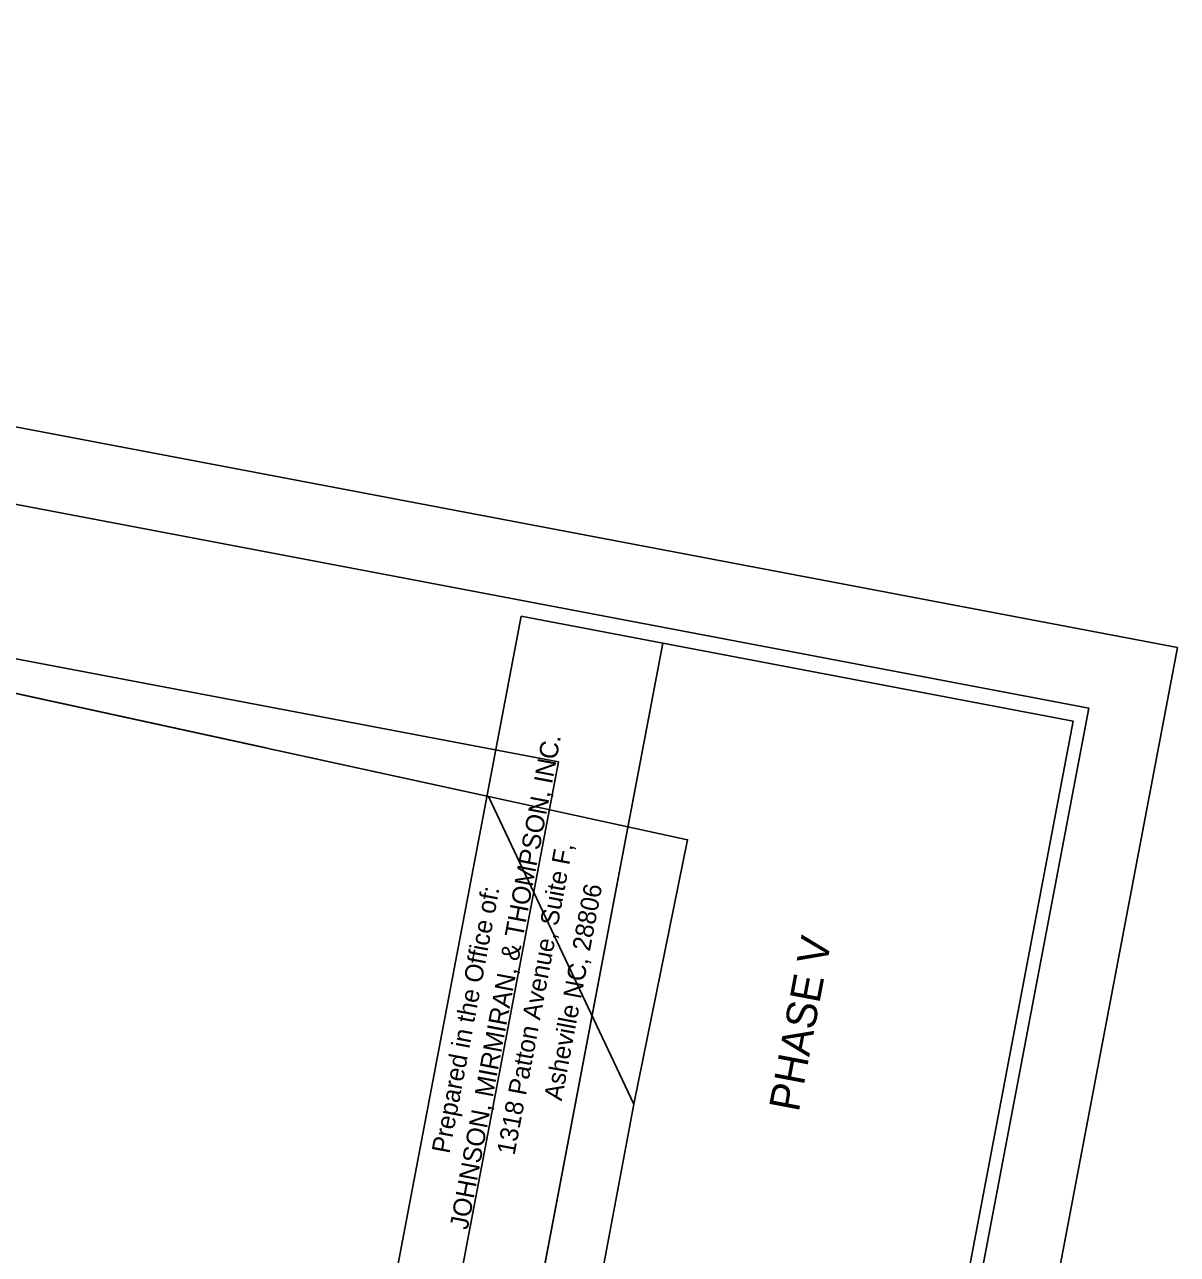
# Model space of a CAD drawing. Extents: x 1615680 to 1617075, y 898420 to 901168.
# Drawn here: x 1616695.7 to 1617075.3, y 900763.4 to 901168.4 of the extents above; entities that cross this region are included whole.
import ezdxf

# ---------------------------------------------------------------- set-up
doc = ezdxf.new("R2010")
doc.units = 0
for name, color, linetype in [('DEV BORDER CELL', 7, 'Continuous'), ('Matchline', 7, 'Continuous'), ('Scratch_Level_0', 7, 'Continuous'), ('Sheet Clip Boundary CELL', 7, 'Continuous'), ('Sheet Plan CELL', 7, 'Continuous'), ('Sheet Plot Border Outside CELL', 7, 'Continuous'), ('Sheet Sticker Preliminary CELL', 7, 'Continuous'), ('Sheet Title CELL', 7, 'Continuous')]:
    doc.layers.add(name, color=color, linetype=linetype)

msp = doc.modelspace()

# ---------------------------------------------------------------- linework, layer by layer
at = {"layer": 'DEV BORDER CELL'}
for points in [[(1616014.55, 901139.21), (1615734.74, 899665.53), (1616766.32, 899469.67), (1617046.12, 900943.35)], [(1616905.88, 900964.73), (1616861.86, 900732.87), (1616996.95, 900707.23), (1617040.97, 900939.08)]]:
    msp.add_lwpolyline(points, close=True, dxfattribs=at)
at = {"layer": 'Matchline'}
msp.add_line((1616176.29, 901060.7), (1616775.18, 900930.23), dxfattribs=at)
at = {"layer": 'Scratch_Level_0'}
msp.add_lwpolyline([(1616054.34, 901080.76), (1615793.19, 899705.33), (1616726.52, 899528.12), (1616890.46, 900391.55), (1616774.26, 900413.61), (1616871.48, 900925.61)], close=True, dxfattribs=at)
at = {"layer": 'Sheet Clip Boundary CELL'}
for points in [[(1616176.29, 901060.7), (1616848.46, 900914.27), (1616896.28, 900812.91), (1616872.94, 900688.21), (1616835.87, 900695.21), (1616753.94, 900262.18), (1616898.09, 900233.43), (1616734.79, 899562.1), (1616202.98, 899609.43), (1616198.71, 899647.14), (1615822.69, 899825.07), (1616054.34, 901080.76)], [(1616176.29, 901060.7), (1616914, 900899.99), (1616896.28, 900812.91), (1616872.94, 900688.21), (1616835.87, 900695.21), (1616753.94, 900262.18), (1616898.09, 900233.43), (1616747.89, 899480.25), (1615915.8, 899646.19), (1615751.76, 899738.03), (1615981.58, 900932.46), (1616145.94, 900899.57)]]:
    msp.add_lwpolyline(points, close=True, dxfattribs=at)
at = {"layer": 'Sheet Plan CELL'}
msp.add_lwpolyline([(1616859.19, 900973.59), (1616804.79, 900687.04), (1616851.47, 900678.18), (1616905.88, 900964.73)], close=True, dxfattribs=at)
at = {"layer": 'Sheet Plot Border Outside CELL'}
for points in [[(1616760.47, 899304.87), (1615679.78, 899510.06), (1615994.65, 901168.43), (1617075.34, 900963.24)], [(1616760.47, 899304.87), (1617075.34, 900963.24), (1615994.65, 901168.43), (1615679.78, 899510.06)]]:
    msp.add_lwpolyline(points, close=True, dxfattribs=at)

# ---------------------------------------------------------------- texts
at = {"layer": 'Sheet Sticker Preliminary CELL'}
msp.add_text('PHASE V', height=10, rotation=79.2494, dxfattribs=at).set_placement((1616950.61, 900810.06))
at = {"layer": 'Sheet Title CELL'}
for s, height, p in [('JOHNSON, MIRMIRAN, & THOMPSON, INC.', 6.0929, (1616841.6, 900771.3)), ('1318 Patton Avenue, Suite F,', 5.9679, (1616857.01, 900795.9)), ('Prepared in the Office of:', 5.9987, (1616835.57, 900796.39)), ('Asheville NC, 28806', 5.9679, (1616872.53, 900813.77))]:
    msp.add_text(s, height=height, rotation=79.301, dxfattribs=at).set_placement(p)

doc.saveas('drawing.dxf')
